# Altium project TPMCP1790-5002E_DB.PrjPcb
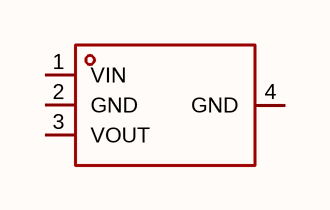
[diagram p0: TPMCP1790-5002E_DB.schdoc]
1 sheet, 1 parts. Net scope: global (net labels, ports and power ports of the same name join across sheets).

## Sheet TPMCP1790-5002E_DB.schdoc
size 127 x 101 mm

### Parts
U?  tpmcp1790-5002e/db  [SOT-223-4_L6.5-W3.5-P2.30-LS7.0-BR]  (value not drawn)

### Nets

Not connected (* = marked no-connect by the designer): U? 1(VIN) 2(GND) 3(VOUT) 4(GND)

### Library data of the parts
U? = tpmcp1790-5002e/db: 输出极性:正极;工作电压:36V;输出电压:5V;输出电流:200mA;电源纹波抑制比(PSRR):70dB;输出类型:固定;; Manufacturer: TECH PUBLIC(台舟); AddInBom: yes; ModelId: 925194bf9823436183a3e0b978a8d076; ModelName: SOT-223-4P_L6.5-W3.5-H1.6-LS7.0-P2.30; ModelTransform: 279.89794,255.905,0,180,0,0,-0.0005,-0.0005,0; Output Configuration: 正极; Voltage - Supply: 36V; Output Voltage: 5V; Output Current: 200mA; Power Supply Rejection Ratio (PSRR): 70dB; Voltage Dropout: 600mV@(100mA); standby current: 1.5uA; Output Type: 固定; Number of Outputs: 1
